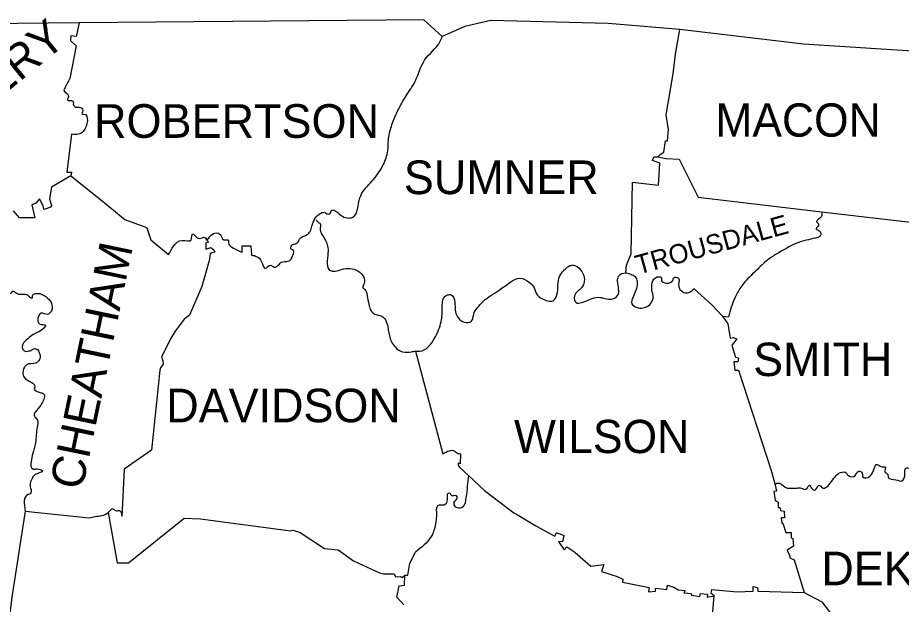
# Model space of a CAD drawing. Extents: x 1623795.1 to 1623879, y 427353.8 to 427391.8.
# Drawn here: x 1623824.175 to 1623825.667, y 427385.316 to 427386.306 of the extents above; entities that cross this region are included whole.
import ezdxf

# ---------------------------------------------------------------- set-up
doc = ezdxf.new("R2010")
doc.units = 0
doc.layers.add('DESIGN - SHEET - Corner Text', color=7, linetype='Continuous')
doc.layers.add('DESIGN - SHEET - Linework', color=7, linetype='Continuous')

msp = doc.modelspace()

# ---------------------------------------------------------------- linework, layer by layer
at = {"layer": 'DESIGN - SHEET - Corner Text'}
for points in [[(1623828.041, 427386.238), (1623827.688, 427386.234), (1623827.41, 427386.228), (1623827.179, 427386.225), (1623826.839, 427386.227), (1623826.302, 427386.256), (1623826.043, 427386.236), (1623825.738, 427386.246), (1623825.502, 427386.261), (1623825.293, 427386.286), (1623825.172, 427386.296), (1623824.974, 427386.301), (1623824.93, 427386.291), (1623824.892, 427386.274), (1623824.861, 427386.302), (1623824.279, 427386.297), (1623823.704, 427386.291)], [(1623824.279, 427386.297), (1623824.274, 427386.274), (1623824.265, 427386.275), (1623824.264, 427386.267), (1623824.274, 427386.258), (1623824.263, 427386.203)], [(1623825.256, 427386.071), (1623825.26, 427386.075), (1623825.266, 427386.079), (1623825.269, 427386.098), (1623825.272, 427386.098), (1623825.274, 427386.117), (1623825.27, 427386.142), (1623825.282, 427386.211), (1623825.286, 427386.244), (1623825.293, 427386.286)], [(1623824.266, 427386.109), (1623824.258, 427386.045), (1623824.266, 427386.045), (1623824.265, 427386.039), (1623824.232, 427386.02), (1623824.229, 427386), (1623824.232, 427385.989), (1623824.231, 427385.986), (1623824.219, 427385.982), (1623824.218, 427385.988), (1623824.212, 427386), (1623824.206, 427385.993), (1623824.199, 427385.99), (1623824.204, 427385.968), (1623824.178, 427385.968), (1623824.168, 427385.98)], [(1623825.202, 427385.875), (1623825.203, 427385.888), (1623825.211, 427385.907), (1623825.213, 427386.028), (1623825.257, 427386.023), (1623825.259, 427386.06), (1623825.247, 427386.065), (1623825.249, 427386.071), (1623825.252, 427386.071), (1623825.256, 427386.071), (1623825.27, 427386.068), (1623825.292, 427386.067), (1623825.324, 427386.003), (1623825.532, 427385.978), (1623825.697, 427385.959)], [(1623824.265, 427386.039), (1623824.312, 427386.001), (1623824.356, 427385.965), (1623824.39, 427385.953), (1623824.393, 427385.951), (1623824.4, 427385.931), (1623824.43, 427385.906)], [(1623824.493, 427385.932), (1623824.498, 427385.927), (1623824.493, 427385.926), (1623824.493, 427385.915), (1623824.501, 427385.918), (1623824.506, 427385.914), (1623824.508, 427385.91), (1623824.503, 427385.909), (1623824.5, 427385.907), (1623824.499, 427385.899), (1623824.498, 427385.894), (1623824.486, 427385.852), (1623824.465, 427385.804), (1623824.456, 427385.797), (1623824.441, 427385.777), (1623824.433, 427385.764), (1623824.418, 427385.733), (1623824.42, 427385.727), (1623824.421, 427385.721), (1623824.416, 427385.715), (1623824.415, 427385.711), (1623824.401, 427385.576), (1623824.355, 427385.544), (1623824.351, 427385.464)], [(1623824.554, 427385.91), (1623824.554, 427385.921), (1623824.569, 427385.921), (1623824.57, 427385.905)], [(1623825.317, 427385.848), (1623825.347, 427385.821), (1623825.365, 427385.802), (1623825.374, 427385.789), (1623825.378, 427385.765), (1623825.383, 427385.766), (1623825.389, 427385.764), (1623825.384, 427385.757), (1623825.381, 427385.753), (1623825.387, 427385.733), (1623825.392, 427385.732), (1623825.391, 427385.725), (1623825.384, 427385.725), (1623825.386, 427385.711), (1623825.392, 427385.711), (1623825.448, 427385.54), (1623825.454, 427385.517), (1623825.456, 427385.507), (1623825.452, 427385.506), (1623825.454, 427385.491), (1623825.459, 427385.488), (1623825.459, 427385.479), (1623825.462, 427385.479), (1623825.463, 427385.474), (1623825.469, 427385.473), (1623825.47, 427385.462), (1623825.464, 427385.462), (1623825.465, 427385.453), (1623825.467, 427385.453), (1623825.472, 427385.437), (1623825.481, 427385.437), (1623825.481, 427385.428), (1623825.484, 427385.427), (1623825.485, 427385.414), (1623825.474, 427385.407), (1623825.479, 427385.397), (1623825.479, 427385.394), (1623825.486, 427385.391), (1623825.503, 427385.336)], [(1623825.365, 427385.802), (1623825.375, 427385.801)], [(1623824.847, 427385.743), (1623824.893, 427385.57)], [(1623824.923, 427385.57), (1623824.922, 427385.553), (1623824.919, 427385.554), (1623824.919, 427385.55), (1623824.922, 427385.546), (1623824.936, 427385.533), (1623824.963, 427385.508), (1623825.013, 427385.47), (1623825.02, 427385.466), (1623825.05, 427385.448), (1623825.082, 427385.431), (1623825.085, 427385.437), (1623825.097, 427385.432), (1623825.095, 427385.421), (1623825.088, 427385.422), (1623825.098, 427385.408), (1623825.102, 427385.413), (1623825.116, 427385.404), (1623825.143, 427385.38), (1623825.165, 427385.383), (1623825.161, 427385.371), (1623825.187, 427385.363), (1623825.197, 427385.358), (1623825.196, 427385.353), (1623825.241, 427385.344), (1623825.24, 427385.337), (1623825.252, 427385.338), (1623825.252, 427385.343), (1623825.271, 427385.341), (1623825.272, 427385.348), (1623825.283, 427385.345), (1623825.29, 427385.34), (1623825.302, 427385.339), (1623825.3, 427385.335), (1623825.312, 427385.334), (1623825.313, 427385.331), (1623825.327, 427385.329), (1623825.328, 427385.334), (1623825.34, 427385.333), (1623825.339, 427385.328), (1623825.351, 427385.33)], [(1623824.188, 427385.473), (1623824.165, 427385.328), (1623824.149, 427385.197), (1623824.128, 427385.032), (1623824.103, 427385.022)], [(1623824.188, 427385.473), (1623824.296, 427385.462)], [(1623824.328, 427385.471), (1623824.343, 427385.386), (1623824.362, 427385.386), (1623824.456, 427385.461), (1623824.484, 427385.46), (1623824.636, 427385.44), (1623824.64, 427385.441), (1623824.652, 427385.437), (1623824.693, 427385.41), (1623824.716, 427385.408), (1623824.742, 427385.389), (1623824.786, 427385.369), (1623824.793, 427385.367), (1623824.811, 427385.367), (1623824.813, 427385.362), (1623824.821, 427385.363), (1623824.824, 427385.361), (1623824.829, 427385.365)], [(1623824.827, 427385.315), (1623824.815, 427385.328), (1623824.819, 427385.347), (1623824.828, 427385.348), (1623824.829, 427385.365), (1623824.834, 427385.365), (1623824.837, 427385.385), (1623824.847, 427385.404)], [(1623825.348, 427385.297), (1623825.351, 427385.33), (1623825.346, 427385.334), (1623825.347, 427385.341), (1623825.39, 427385.337), (1623825.417, 427385.338), (1623825.417, 427385.346), (1623825.424, 427385.344), (1623825.425, 427385.338), (1623825.503, 427385.336), (1623825.533, 427385.32), (1623825.575, 427385.265)]]:
    msp.add_lwpolyline(points, dxfattribs=at)
for points in [[(1623824.57, 427385.905), (1623824.578, 427385.903), (1623824.587, 427385.894), (1623824.593, 427385.883), (1623824.602, 427385.888), (1623824.608, 427385.885), (1623824.617, 427385.89), (1623824.62, 427385.893), (1623824.632, 427385.895), (1623824.637, 427385.899), (1623824.64, 427385.906), (1623824.641, 427385.913), (1623824.637, 427385.915), (1623824.638, 427385.922), (1623824.644, 427385.924), (1623824.649, 427385.928), (1623824.651, 427385.932), (1623824.653, 427385.934), (1623824.664, 427385.94), (1623824.669, 427385.945), (1623824.672, 427385.954), (1623824.687, 427385.976), (1623824.694, 427385.977), (1623824.697, 427385.975), (1623824.702, 427385.975), (1623824.706, 427385.981), (1623824.709, 427385.981), (1623824.721, 427385.972), (1623824.741, 427385.969), (1623824.753, 427386.002), (1623824.768, 427386.024), (1623824.787, 427386.048), (1623824.797, 427386.069), (1623824.8, 427386.081), (1623824.801, 427386.099), (1623824.806, 427386.122), (1623824.81, 427386.134), (1623824.817, 427386.149), (1623824.831, 427386.174), (1623824.846, 427386.198), (1623824.862, 427386.234), (1623824.888, 427386.265), (1623824.892, 427386.274)], [(1623824.263, 427386.203), (1623824.254, 427386.186), (1623824.253, 427386.184), (1623824.259, 427386.177), (1623824.261, 427386.173), (1623824.259, 427386.167), (1623824.264, 427386.166), (1623824.269, 427386.164), (1623824.269, 427386.16), (1623824.273, 427386.155), (1623824.279, 427386.155), (1623824.285, 427386.149), (1623824.284, 427386.143), (1623824.286, 427386.143), (1623824.286, 427386.114), (1623824.278, 427386.109), (1623824.266, 427386.109)], [(1623825.532, 427385.978), (1623825.532, 427385.97), (1623825.524, 427385.961), (1623825.527, 427385.958), (1623825.525, 427385.952), (1623825.523, 427385.95), (1623825.527, 427385.947), (1623825.531, 427385.942), (1623825.53, 427385.937), (1623825.526, 427385.935), (1623825.495, 427385.927), (1623825.46, 427385.909), (1623825.444, 427385.899), (1623825.424, 427385.881), (1623825.403, 427385.86), (1623825.396, 427385.851), (1623825.386, 427385.833), (1623825.375, 427385.801)], [(1623824.679, 427385.965), (1623824.682, 427385.961), (1623824.686, 427385.958), (1623824.686, 427385.951), (1623824.695, 427385.93), (1623824.699, 427385.909), (1623824.703, 427385.879), (1623824.711, 427385.878), (1623824.722, 427385.881), (1623824.75, 427385.878), (1623824.76, 427385.857), (1623824.758, 427385.85), (1623824.761, 427385.847), (1623824.765, 427385.837), (1623824.768, 427385.822), (1623824.775, 427385.807), (1623824.79, 427385.802), (1623824.796, 427385.796), (1623824.8, 427385.784), (1623824.804, 427385.764), (1623824.817, 427385.746), (1623824.825, 427385.742), (1623824.84, 427385.742), (1623824.847, 427385.743), (1623824.854, 427385.743), (1623824.879, 427385.765), (1623824.89, 427385.793), (1623824.892, 427385.817), (1623824.893, 427385.829), (1623824.896, 427385.835), (1623824.901, 427385.838), (1623824.907, 427385.838), (1623824.913, 427385.826), (1623824.914, 427385.812), (1623824.917, 427385.802), (1623824.929, 427385.792), (1623824.941, 427385.793), (1623824.945, 427385.805), (1623824.951, 427385.816), (1623824.974, 427385.837), (1623824.988, 427385.846), (1623825.006, 427385.859), (1623825.023, 427385.866), (1623825.039, 427385.859), (1623825.047, 427385.85), (1623825.052, 427385.838), (1623825.06, 427385.832), (1623825.07, 427385.828), (1623825.079, 427385.828), (1623825.084, 427385.834), (1623825.089, 427385.866), (1623825.095, 427385.877), (1623825.101, 427385.883), (1623825.11, 427385.888), (1623825.123, 427385.883), (1623825.131, 427385.857), (1623825.127, 427385.85), (1623825.115, 427385.836), (1623825.118, 427385.825), (1623825.127, 427385.825), (1623825.155, 427385.834), (1623825.167, 427385.832), (1623825.178, 427385.831), (1623825.188, 427385.837), (1623825.188, 427385.861), (1623825.19, 427385.87), (1623825.202, 427385.875), (1623825.212, 427385.872), (1623825.219, 427385.867), (1623825.221, 427385.858), (1623825.214, 427385.834), (1623825.212, 427385.823), (1623825.22, 427385.817), (1623825.231, 427385.816), (1623825.245, 427385.825), (1623825.248, 427385.834), (1623825.246, 427385.846), (1623825.246, 427385.855), (1623825.252, 427385.867), (1623825.262, 427385.867), (1623825.262, 427385.863), (1623825.281, 427385.862), (1623825.283, 427385.867), (1623825.291, 427385.866), (1623825.291, 427385.856), (1623825.3, 427385.842), (1623825.308, 427385.842), (1623825.318, 427385.849)], [(1623824.43, 427385.906), (1623824.438, 427385.92), (1623824.453, 427385.93), (1623824.468, 427385.931), (1623824.47, 427385.941), (1623824.482, 427385.933), (1623824.491, 427385.935), (1623824.494, 427385.932), (1623824.502, 427385.939), (1623824.517, 427385.94), (1623824.523, 427385.931), (1623824.531, 427385.93), (1623824.531, 427385.926), (1623824.536, 427385.919), (1623824.554, 427385.91)], [(1623824.037, 427385.849), (1623824.045, 427385.85), (1623824.046, 427385.855), (1623824.054, 427385.853), (1623824.055, 427385.848), (1623824.06, 427385.846), (1623824.061, 427385.851), (1623824.073, 427385.852), (1623824.125, 427385.854), (1623824.129, 427385.855), (1623824.133, 427385.866), (1623824.139, 427385.867), (1623824.155, 427385.844), (1623824.165, 427385.842), (1623824.166, 427385.844), (1623824.173, 427385.841), (1623824.187, 427385.839), (1623824.193, 427385.837), (1623824.198, 427385.833), (1623824.2, 427385.833), (1623824.2, 427385.837), (1623824.202, 427385.839), (1623824.228, 427385.83), (1623824.232, 427385.824), (1623824.232, 427385.811), (1623824.225, 427385.805), (1623824.215, 427385.807), (1623824.212, 427385.789), (1623824.222, 427385.787), (1623824.216, 427385.779), (1623824.201, 427385.771), (1623824.192, 427385.764), (1623824.185, 427385.757), (1623824.183, 427385.753), (1623824.184, 427385.746), (1623824.188, 427385.743), (1623824.193, 427385.743), (1623824.199, 427385.745), (1623824.202, 427385.747), (1623824.209, 427385.745), (1623824.212, 427385.739), (1623824.213, 427385.732), (1623824.21, 427385.726), (1623824.206, 427385.723), (1623824.19, 427385.72), (1623824.186, 427385.715), (1623824.184, 427385.707), (1623824.186, 427385.699), (1623824.204, 427385.682), (1623824.203, 427385.679), (1623824.206, 427385.676), (1623824.213, 427385.673), (1623824.22, 427385.67), (1623824.22, 427385.664), (1623824.216, 427385.655), (1623824.207, 427385.643), (1623824.203, 427385.636), (1623824.205, 427385.631), (1623824.209, 427385.625), (1623824.208, 427385.615), (1623824.205, 427385.588), (1623824.202, 427385.544), (1623824.211, 427385.544), (1623824.217, 427385.541), (1623824.205, 427385.535), (1623824.2, 427385.529), (1623824.196, 427385.516), (1623824.197, 427385.512), (1623824.196, 427385.502), (1623824.193, 427385.501), (1623824.188, 427385.473)], [(1623824.893, 427385.57), (1623824.904, 427385.575), (1623824.912, 427385.575), (1623824.917, 427385.571), (1623824.923, 427385.57)], [(1623825.454, 427385.517), (1623825.457, 427385.52), (1623825.462, 427385.52), (1623825.474, 427385.512), (1623825.484, 427385.512), (1623825.491, 427385.512), (1623825.498, 427385.512), (1623825.506, 427385.51), (1623825.512, 427385.517), (1623825.518, 427385.509), (1623825.522, 427385.509), (1623825.528, 427385.517), (1623825.533, 427385.513), (1623825.549, 427385.523), (1623825.567, 427385.539), (1623825.572, 427385.539), (1623825.578, 427385.533), (1623825.589, 427385.533), (1623825.594, 427385.54), (1623825.6, 427385.539), (1623825.602, 427385.531), (1623825.614, 427385.532), (1623825.626, 427385.552), (1623825.634, 427385.548), (1623825.64, 427385.547), (1623825.639, 427385.54), (1623825.644, 427385.535), (1623825.645, 427385.53), (1623825.658, 427385.526), (1623825.668, 427385.524), (1623825.673, 427385.537), (1623825.674, 427385.545), (1623825.684, 427385.545), (1623825.692, 427385.543), (1623825.695, 427385.546), (1623825.7, 427385.557), (1623825.704, 427385.555), (1623825.708, 427385.556), (1623825.712, 427385.561), (1623825.721, 427385.567), (1623825.73, 427385.564), (1623825.737, 427385.56), (1623825.738, 427385.555), (1623825.741, 427385.545), (1623825.746, 427385.533), (1623825.752, 427385.526), (1623825.76, 427385.529), (1623825.77, 427385.511), (1623825.767, 427385.499), (1623825.767, 427385.493), (1623825.764, 427385.491), (1623825.771, 427385.487), (1623825.773, 427385.484), (1623825.782, 427385.48), (1623825.79, 427385.489), (1623825.808, 427385.49), (1623825.815, 427385.49), (1623825.822, 427385.497), (1623825.83, 427385.492), (1623825.852, 427385.487), (1623825.856, 427385.489)], [(1623824.936, 427385.533), (1623824.932, 427385.496), (1623824.926, 427385.48), (1623824.922, 427385.478), (1623824.913, 427385.482), (1623824.913, 427385.49), (1623824.917, 427385.495), (1623824.916, 427385.499), (1623824.908, 427385.499), (1623824.905, 427385.503), (1623824.902, 427385.503), (1623824.9, 427385.498), (1623824.9, 427385.492), (1623824.897, 427385.484), (1623824.89, 427385.483), (1623824.884, 427385.482), (1623824.882, 427385.477), (1623824.882, 427385.471), (1623824.88, 427385.449), (1623824.877, 427385.438), (1623824.873, 427385.43), (1623824.847, 427385.404)], [(1623824.296, 427385.462), (1623824.306, 427385.464), (1623824.328, 427385.471), (1623824.336, 427385.477), (1623824.34, 427385.474), (1623824.347, 427385.474), (1623824.351, 427385.464)]]:
    msp.add_spline(points, degree=3, dxfattribs=at)

# ---------------------------------------------------------------- texts
at = {"layer": 'DESIGN - SHEET - Linework'}
for s, height, rotation, p in [('MONTGOMERY', 0.05638, 39.0648, (1623823.827, 427385.912)), ('TROUSDALE', 0.03249, 15.4222, (1623825.223, 427385.872)), ('CHEATHAM', 0.05615, 78.252, (1623824.284, 427385.507))]:
    msp.add_text(s, height=height, rotation=rotation, dxfattribs=at).set_placement(p)
for s, height, p in [('ROBERTSON', 0.05681, (1623824.304, 427386.103)), ('MACON', 0.05608, (1623825.353, 427386.105)), ('SUMNER', 0.05681, (1623824.827, 427386.008)), ('SMITH', 0.05639, (1623825.417, 427385.701)), ('DAVIDSON', 0.05668, (1623824.426, 427385.623)), ('WILSON', 0.05608, (1623825.013, 427385.571)), ('DEKALB', 0.05668, (1623825.532, 427385.348))]:
    msp.add_text(s, height=height, dxfattribs=at).set_placement(p)

doc.saveas('drawing.dxf')
